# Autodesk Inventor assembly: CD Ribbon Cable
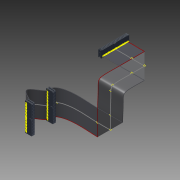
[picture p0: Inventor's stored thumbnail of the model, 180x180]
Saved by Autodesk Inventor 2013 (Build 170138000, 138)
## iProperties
Created: 2007-02
Part Number: CD Ribbon Cable
Document SubType Name: Assembly
Designer: Autodesk Inc.
Mass: 12.1553 g
Surface Area: 105.882 cm^2
Volume: 12.1553 cm^3
Density: 1 g/cm^3
Part Number: 28AWG_40Con.RibbonCable1
Material: Default
Description: 28AWG_40Con
Company: Autodesk Inc.
HarnessSettings: <HarnessSettings><Defaults><Segments><Diameter value="0.200 in" fromwires="True"/><Offset value="0.100 in"/><ColorStyle value="Blue"/><RoundUp value=""/><BendRa
CableDummyParamRefKey: Key:16|2|0|0|16|0|0|0|198|2|0|0|0|0|0|0|129|0|0|0|0|0|0|0|Level:1
ParentFileIdentifier: 5|1|0|0|190|1|0|0|80|0|65|0|84|0|72|0|83|0|59|0|67|0|58|0|92|0|77|0|121|0|32|0|68|0|111|0|99|0|117|0|109|0|101|0|110|0|116|0|115|0|92|0|73|0|110|0|118|0|101|0|1
Title: Personal Computer
Author: Autodesk Inc.
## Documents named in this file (3)
- Z:\_DATEN\Personal Computer\Aip\CD Ribbon Cable.iam
- Z:\_DATEN\Personal Computer\Aip\CD Ribbon Cable.ipt
- Z:\_DATEN\Personal Computer\Aip\Ribbon Cable Connector.ipt
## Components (5 placed, 3 different names)
1. CD Ribbon Cable
2. Ribbon Cable Connector:1
3. Ribbon Cable Connector:2
4. Ribbon Cable Connector:3
5. HA_VC_100:1
